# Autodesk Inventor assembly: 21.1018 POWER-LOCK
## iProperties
Created: 2006-12
Part Number: 21.1018 POWER-LOCK
Document SubType Name: Assembly
Designer: Andy Moles
Mass: 31.6248 g
Surface Area: 33.9718 cm^2
Volume: 4.02562 cm^3
Density: 7.8559 g/cm^3
Author: Andy Moles
